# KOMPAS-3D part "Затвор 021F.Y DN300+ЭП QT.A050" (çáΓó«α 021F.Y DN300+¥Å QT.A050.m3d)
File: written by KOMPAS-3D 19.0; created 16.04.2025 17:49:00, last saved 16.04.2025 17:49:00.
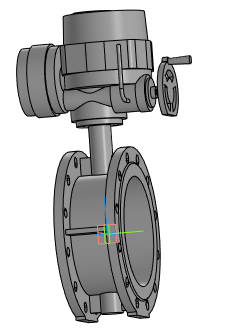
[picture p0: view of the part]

Document properties: Полное имя файла: Затвор 021F.Y DN300+ЭП QT.A050.a3d

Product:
- Part/product: Затвор 021F.Y DN300+ЭП QT.A050
    Масса: 178.775

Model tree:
1. Операция без истории:1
